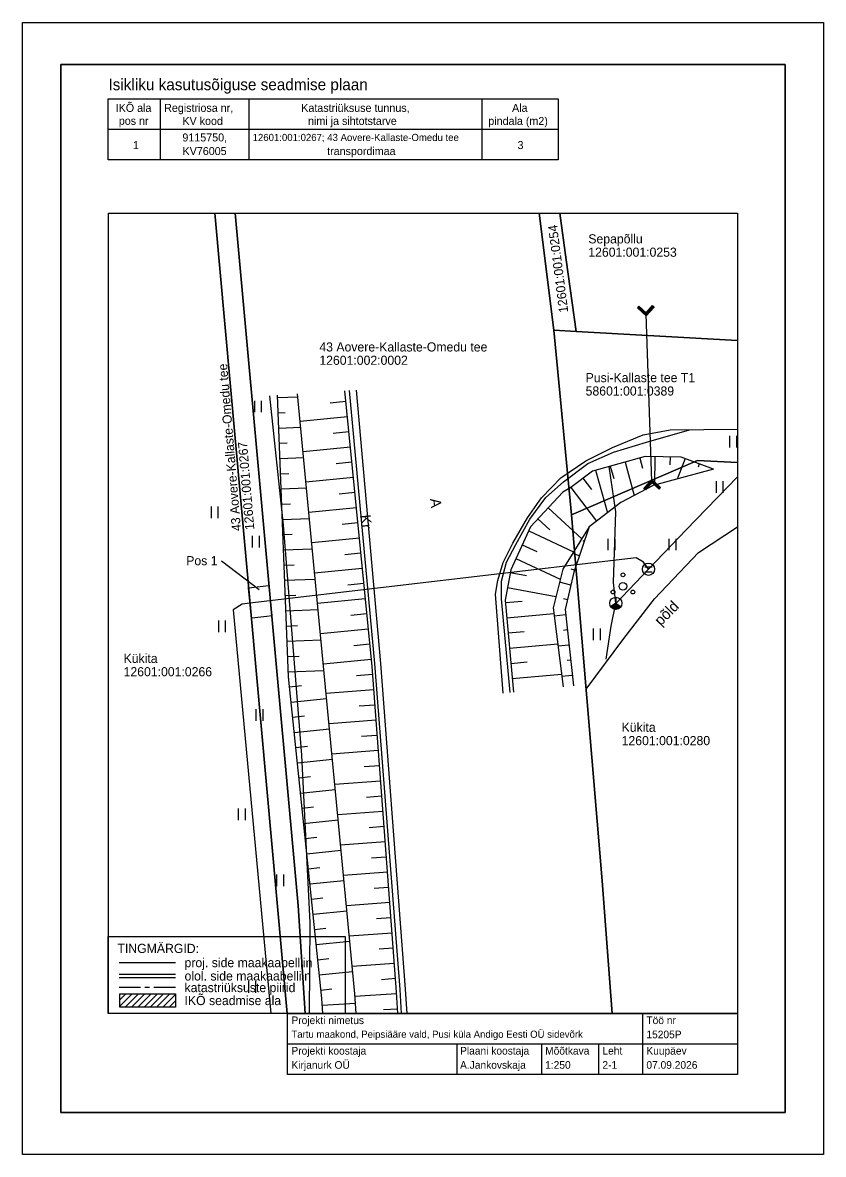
# Model space of a CAD drawing. Extents: x 683366.9 to 683419.4, y 6504541.6 to 6504615.8.
import ezdxf

# ---------------------------------------------------------------- set-up
doc = ezdxf.new("R2010")
doc.units = 0
for name, color, linetype in [('HALJASTUS', 7, 'Continuous'), ('KASUTUSALA', 7, 'Continuous'), ('PIIR', 7, 'Continuous'), ('PR_SIDE', 7, 'Continuous'), ('PUU', 7, 'Continuous'), ('RELJEEF', 7, 'Continuous'), ('SIKAEV', 7, 'Continuous'), ('SITRASS', 7, 'Continuous'), ('TEE', 7, 'Continuous'), ('TRUUP', 7, 'Continuous'), ('VORMISTUS', 7, 'Continuous')]:
    doc.layers.add(name, color=color, linetype=linetype)

msp = doc.modelspace()

# ---------------------------------------------------------------- linework, layer by layer
at = {"layer": 'HALJASTUS'}
for p, q in [((683382.127, 6504591.003), (683382.127, 6504590.242)), ((683382.583, 6504591.003), (683382.583, 6504590.242)), ((683413.292, 6504588.688), (683413.292, 6504587.927)), ((683413.747, 6504588.688), (683413.747, 6504587.927)), ((683412.397, 6504585.715), (683412.397, 6504584.954)), ((683412.852, 6504585.715), (683412.852, 6504584.954)), ((683379.285, 6504584.061), (683379.285, 6504583.3)), ((683379.74, 6504584.061), (683379.74, 6504583.3)), ((683381.983, 6504582.132), (683381.983, 6504581.371)), ((683382.438, 6504582.132), (683382.438, 6504581.371)), ((683405.305, 6504581.949), (683405.305, 6504581.188)), ((683405.76, 6504581.949), (683405.76, 6504581.188)), ((683409.309, 6504581.949), (683409.309, 6504581.188)), ((683409.764, 6504581.949), (683409.764, 6504581.188)), ((683379.767, 6504576.588), (683379.767, 6504575.827)), ((683380.222, 6504576.588), (683380.222, 6504575.827)), ((683404.34, 6504576.059), (683404.34, 6504575.298)), ((683404.795, 6504576.059), (683404.795, 6504575.298)), ((683382.224, 6504570.755), (683382.224, 6504569.993)), ((683382.679, 6504570.755), (683382.679, 6504569.993)), ((683381.068, 6504564.246), (683381.068, 6504563.485)), ((683381.523, 6504564.246), (683381.523, 6504563.485)), ((683383.573, 6504559.907), (683383.573, 6504559.146)), ((683384.028, 6504559.907), (683384.028, 6504559.146)), ((683381.742, 6504552.916), (683381.742, 6504552.155)), ((683382.197, 6504552.916), (683382.197, 6504552.155))]:
    msp.add_line(p, q, dxfattribs=at)
msp.add_lwpolyline([(683403.882, 6504572.085), (683406.35, 6504575.392), (683408.363, 6504577.994), (683411.241, 6504581.038), (683413.81, 6504582.721)], dxfattribs=at)
at = {"layer": 'KASUTUSALA'}
msp.add_lwpolyline([(683383.083, 6504578.873), (683383.264, 6504576.881), (683382.95, 6504576.844), (683382.95, 6504576.843), (683381.957, 6504576.727), (683381.931, 6504576.724), (683381.751, 6504578.716)], close=True, dxfattribs=at)
at = {"layer": 'PIIR'}
for p, q in [((683384.272, 6504550.807), (683379.529, 6504603.307)), ((683379.529, 6504603.307), (683384.272, 6504550.807))]:
    msp.add_line(p, q, dxfattribs=at)
for points in [[(683385.461, 6504550.807), (683384.99, 6504557.89), (683380.863, 6504603.307)], [(683380.863, 6504603.307), (683384.99, 6504557.89), (683385.461, 6504550.807)], [(683400.81, 6504603.307), (683401.76, 6504595.62), (683403.22, 6504595.54), (683402.57, 6504600.25), (683402.154, 6504603.307)], [(683405.591, 6504550.807), (683404.93, 6504559.51), (683402.93, 6504583.52), (683401.76, 6504595.62), (683400.81, 6504603.307)], [(683402.154, 6504603.307), (683402.57, 6504600.25), (683403.22, 6504595.54), (683413.81, 6504594.943)], [(683413.81, 6504594.943), (683403.22, 6504595.54), (683401.76, 6504595.62), (683402.93, 6504583.52), (683411.18, 6504587.08), (683413.81, 6504586.956)], [(683413.81, 6504586.956), (683411.18, 6504587.08), (683402.93, 6504583.52), (683404.93, 6504559.51), (683405.591, 6504550.807)]]:
    msp.add_lwpolyline(points, dxfattribs=at)
at = {"layer": 'PR_SIDE'}
for p, q in [((683405.828, 6504577.696), (683407.97, 6504579.943)), ((683407.737, 6504580.103), (683408.202, 6504580.103)), ((683407.737, 6504579.783), (683408.202, 6504579.783))]:
    msp.add_line(p, q, dxfattribs=at)
for points in [[(683407.97, 6504579.943), (683410.435, 6504582.529), (683413.81, 6504586.014)], [(683407.97, 6504579.943), (683407.639, 6504580.418), (683407.152, 6504580.701), (683381.841, 6504577.72)], [(683381.841, 6504577.72), (683381.328, 6504577.66), (683380.736, 6504577.291), (683383.213, 6504550.807)]]:
    msp.add_lwpolyline(points, dxfattribs=at)
msp.add_circle((683407.97, 6504579.943), 0.4, dxfattribs=at)
at = {"layer": 'PUU'}
for centre, radius in [((683406.294, 6504579.574), 0.125), ((683405.644, 6504578.449), 0.125), ((683406.294, 6504578.824), 0.25), ((683406.944, 6504578.449), 0.125)]:
    msp.add_circle(centre, radius, dxfattribs=at)
at = {"layer": 'RELJEEF'}
for p, q in [((683383.661, 6504591.209), (683384.973, 6504591.259)), ((683388.128, 6504590.944), (683387.096, 6504590.843)), ((683383.7, 6504590.21), (683384.156, 6504590.227)), ((683388.226, 6504589.949), (683385.128, 6504589.644)), ((683383.738, 6504589.21), (683385.164, 6504589.265)), ((683388.324, 6504588.954), (683387.29, 6504588.852)), ((683383.776, 6504588.211), (683384.271, 6504588.23)), ((683388.422, 6504587.959), (683385.319, 6504587.653)), ((683383.815, 6504587.212), (683385.355, 6504587.271)), ((683388.52, 6504586.964), (683387.485, 6504586.862)), ((683405.467, 6504586.709), (683405.687, 6504585.905)), ((683406.432, 6504586.974), (683407.033, 6504584.779)), ((683407.396, 6504587.238), (683407.577, 6504586.577)), ((683408.383, 6504587.326), (683408.363, 6504585.459)), ((683409.383, 6504587.315), (683409.377, 6504586.787)), ((683410.366, 6504587.214), (683409.855, 6504585.863)), ((683411.301, 6504586.86), (683411.216, 6504586.635)), ((683383.853, 6504586.213), (683384.386, 6504586.233)), ((683388.618, 6504585.969), (683385.509, 6504585.662)), ((683403.669, 6504585.916), (683404.23, 6504585.177)), ((683404.503, 6504586.445), (683405.272, 6504583.637)), ((683412.237, 6504586.506), (683412.237, 6504586.506)), ((683383.891, 6504585.213), (683385.546, 6504585.277)), ((683402.873, 6504585.311), (683404.559, 6504583.089)), ((683388.716, 6504584.973), (683387.679, 6504584.871)), ((683383.93, 6504584.214), (683384.5, 6504584.236)), ((683388.815, 6504583.978), (683385.7, 6504583.671)), ((683401.4, 6504583.978), (683403.59, 6504581.939)), ((683383.968, 6504583.215), (683385.737, 6504583.283)), ((683388.913, 6504582.983), (683387.874, 6504582.881)), ((683400.719, 6504583.246), (683401.495, 6504582.523)), ((683384.006, 6504582.216), (683384.615, 6504582.239)), ((683400.114, 6504582.462), (683403.062, 6504581.098)), ((683404.082, 6504582.722), (683404.082, 6504582.722)), ((683389.011, 6504581.988), (683385.891, 6504581.68)), ((683399.694, 6504581.555), (683400.638, 6504581.118)), ((683403.764, 6504581.774), (683403.687, 6504581.799)), ((683384.045, 6504581.216), (683385.928, 6504581.289)), ((683389.109, 6504580.993), (683388.068, 6504580.89)), ((683403.446, 6504580.826), (683402.987, 6504580.979)), ((683384.083, 6504580.217), (683384.73, 6504580.242)), ((683389.207, 6504579.998), (683386.081, 6504579.689)), ((683399.274, 6504580.647), (683402.184, 6504579.301)), ((683403.129, 6504579.877), (683402.899, 6504579.954)), ((683384.121, 6504579.218), (683386.119, 6504579.294)), ((683398.901, 6504579.725), (683399.982, 6504579.528)), ((683389.305, 6504579.002), (683388.262, 6504578.9)), ((683398.722, 6504578.741), (683401.904, 6504578.161)), ((683402.886, 6504578.908), (683402.132, 6504579.087)), ((683384.16, 6504578.219), (683384.845, 6504578.245)), ((683389.403, 6504578.007), (683386.272, 6504577.699)), ((683398.586, 6504577.755), (683399.683, 6504577.855)), ((683402.655, 6504577.935), (683402.401, 6504577.995)), ((683384.198, 6504577.219), (683386.31, 6504577.3)), ((683389.501, 6504577.012), (683388.457, 6504576.909)), ((683398.677, 6504576.759), (683401.769, 6504577.041)), ((683402.539, 6504576.955), (683401.79, 6504576.873)), ((683384.236, 6504576.22), (683384.959, 6504576.248)), ((683389.599, 6504576.017), (683386.463, 6504575.708)), ((683398.767, 6504575.763), (683399.81, 6504575.858)), ((683402.648, 6504575.96), (683402.404, 6504575.934)), ((683384.275, 6504575.221), (683386.501, 6504575.306)), ((683389.698, 6504575.022), (683388.651, 6504574.918)), ((683398.858, 6504574.768), (683402.021, 6504575.056)), ((683402.756, 6504574.966), (683402.042, 6504574.888)), ((683384.313, 6504574.222), (683385.074, 6504574.251)), ((683389.796, 6504574.026), (683386.653, 6504573.717)), ((683384.351, 6504573.222), (683386.692, 6504573.312)), ((683398.949, 6504573.772), (683400.015, 6504573.869)), ((683402.865, 6504573.972), (683402.632, 6504573.947)), ((683389.881, 6504573.03), (683388.835, 6504572.952)), ((683399.039, 6504572.776), (683402.273, 6504573.07)), ((683402.973, 6504572.978), (683402.294, 6504572.904)), ((683384.433, 6504572.226), (683385.213, 6504572.307)), ((683389.956, 6504572.033), (683386.836, 6504571.799)), ((683384.536, 6504571.231), (683386.867, 6504571.472)), ((683390.031, 6504571.036), (683388.998, 6504570.958)), ((683384.638, 6504570.237), (683385.413, 6504570.317)), ((683390.106, 6504570.039), (683387.025, 6504569.807)), ((683384.741, 6504569.242), (683387.056, 6504569.481)), ((683390.181, 6504569.041), (683389.16, 6504568.965)), ((683384.844, 6504568.247), (683385.613, 6504568.327)), ((683390.256, 6504568.044), (683387.214, 6504567.816)), ((683384.947, 6504567.253), (683387.245, 6504567.49)), ((683390.33, 6504567.047), (683389.323, 6504566.971)), ((683385.05, 6504566.258), (683385.813, 6504566.337)), ((683390.405, 6504566.05), (683387.403, 6504565.825)), ((683385.152, 6504565.263), (683387.434, 6504565.499)), ((683385.255, 6504564.268), (683386.013, 6504564.347)), ((683390.48, 6504565.053), (683389.486, 6504564.978)), ((683390.555, 6504564.055), (683387.592, 6504563.833)), ((683385.358, 6504563.274), (683387.623, 6504563.508)), ((683390.63, 6504563.058), (683389.649, 6504562.985)), ((683385.461, 6504562.279), (683386.213, 6504562.357)), ((683385.563, 6504561.284), (683387.812, 6504561.517)), ((683390.704, 6504562.061), (683387.781, 6504561.842)), ((683390.779, 6504561.064), (683389.812, 6504560.991)), ((683385.666, 6504560.29), (683386.413, 6504560.367)), ((683390.854, 6504560.067), (683387.971, 6504559.85)), ((683385.769, 6504559.295), (683388.001, 6504559.526)), ((683390.929, 6504559.069), (683389.974, 6504558.998)), ((683385.872, 6504558.3), (683386.613, 6504558.377)), ((683391.004, 6504558.072), (683388.16, 6504557.859)), ((683385.975, 6504557.305), (683388.19, 6504557.534)), ((683391.079, 6504557.075), (683390.137, 6504557.004)), ((683386.077, 6504556.311), (683386.813, 6504556.387)), ((683386.18, 6504555.316), (683388.379, 6504555.543)), ((683391.153, 6504556.078), (683388.349, 6504555.867)), ((683391.228, 6504555.081), (683390.3, 6504555.011)), ((683386.283, 6504554.321), (683387.013, 6504554.397)), ((683391.303, 6504554.084), (683388.538, 6504553.876)), ((683386.386, 6504553.327), (683388.569, 6504553.552)), ((683391.378, 6504553.086), (683390.463, 6504553.018)), ((683386.488, 6504552.332), (683387.213, 6504552.407)), ((683391.451, 6504552.089), (683388.719, 6504551.92)), ((683386.576, 6504551.336), (683388.749, 6504551.484)), ((683391.513, 6504551.091), (683390.604, 6504551.035))]:
    msp.add_line(p, q, dxfattribs=at)
for points in [[(683386.612, 6504550.807), (683386.546, 6504551.775), (683384.364, 6504572.893), (683383.655, 6504591.362)], [(683388.795, 6504550.807), (683388.707, 6504552.098), (683386.71, 6504573.129), (683384.955, 6504591.445)], [(683391.531, 6504550.807), (683391.445, 6504552.197), (683389.841, 6504573.563), (683388.059, 6504591.641)], [(683412.237, 6504586.506), (683410.12, 6504587.307), (683407.743, 6504587.333), (683404.29, 6504586.387), (683402.87, 6504585.309)], [(683412.237, 6504586.506), (683408.284, 6504585.438), (683406.155, 6504584.316), (683404.082, 6504582.722), (683404.082, 6504582.722)], [(683402.87, 6504585.309), (683402.87, 6504585.309), (683402.349, 6504584.997), (683400.237, 6504582.728), (683398.935, 6504579.914), (683398.571, 6504577.917), (683399.12, 6504571.889)], [(683404.082, 6504582.722), (683402.347, 6504579.959), (683401.721, 6504577.418), (683402.38, 6504572.223)], [(683404.082, 6504582.722), (683403.085, 6504579.748), (683402.503, 6504577.293), (683403.048, 6504572.292)]]:
    msp.add_lwpolyline(points, dxfattribs=at)
at = {"layer": 'SIKAEV'}
for p, q in [((683405.831, 6504577.71), (683405.499, 6504577.49)), ((683405.831, 6504578.11), (683405.831, 6504577.71)), ((683405.831, 6504577.71), (683406.163, 6504577.49))]:
    msp.add_line(p, q, dxfattribs=at)
msp.add_circle((683405.831, 6504577.71), 0.4, dxfattribs=at)
for radius in [0.38, 0.36, 0.34, 0.32, 0.3, 0.28, 0.26, 0.24, 0.22, 0.2, 0.18, 0.16, 0.14, 0.12, 0.1, 0.08, 0.06, 0.04]:
    msp.add_arc((683405.831, 6504577.71), radius, 213.53047, 326.46953, dxfattribs=at)
at = {"layer": 'SITRASS'}
for points in [[(683385.753, 6504550.807), (683385.785, 6504556.743), (683385.248, 6504567.755), (683384.036, 6504582.83), (683383.136, 6504591.331)], [(683405.195, 6504574.053), (683405.532, 6504576.217), (683405.831, 6504577.71), (683405.671, 6504579.075), (683405.836, 6504583.714), (683405.386, 6504586.687)]]:
    msp.add_lwpolyline(points, dxfattribs=at)
at = {"layer": 'TEE'}
msp.add_line((683409.392, 6504589.092), (683413.81, 6504589.126), dxfattribs=at)
for points in [[(683391.772, 6504550.807), (683391.678, 6504552.377), (683390.017, 6504573.76), (683388.371, 6504591.661)], [(683392.145, 6504550.807), (683392.042, 6504552.398), (683390.421, 6504573.765), (683388.835, 6504591.69)], [(683398.434, 6504571.819), (683397.934, 6504578.302), (683398.099, 6504579.204), (683398.449, 6504580.382), (683399.075, 6504581.656), (683400.042, 6504583.318), (683400.952, 6504584.633), (683402.217, 6504585.941), (683403.853, 6504587.052), (683405.602, 6504587.93), (683407.625, 6504588.773), (683409.392, 6504589.092)], [(683398.891, 6504571.866), (683398.331, 6504578.013), (683398.331, 6504579.152), (683398.663, 6504580.415), (683399.274, 6504581.57), (683400.189, 6504583.227), (683401.247, 6504584.642), (683402.407, 6504585.68), (683403.985, 6504586.892), (683405.667, 6504587.617), (683407.83, 6504588.292), (683410.648, 6504589.102)]]:
    msp.add_lwpolyline(points, dxfattribs=at)
at = {"layer": 'TRUUP'}
for p, q in [((683407.343, 6504597.208), (683407.246, 6504597.103)), ((683407.246, 6504597.103), (683407.816, 6504596.573)), ((683407.266, 6504597.125), (683407.289, 6504597.064)), ((683407.285, 6504597.145), (683407.329, 6504597.026)), ((683407.294, 6504597.156), (683407.812, 6504596.674)), ((683407.304, 6504597.166), (683407.37, 6504596.988)), ((683407.323, 6504597.186), (683407.411, 6504596.95)), ((683407.342, 6504597.207), (683407.451, 6504596.912)), ((683407.343, 6504597.208), (683407.808, 6504596.775)), ((683407.382, 6504597.171), (683407.492, 6504596.875)), ((683407.423, 6504597.133), (683407.533, 6504596.837)), ((683407.463, 6504597.096), (683407.573, 6504596.799)), ((683407.504, 6504597.058), (683407.614, 6504596.761)), ((683407.545, 6504597.02), (683407.655, 6504596.723)), ((683407.808, 6504596.775), (683408.242, 6504597.24)), ((683407.812, 6504596.674), (683408.294, 6504597.192)), ((683407.816, 6504596.573), (683408.346, 6504597.143)), ((683408.028, 6504597.011), (683408.083, 6504596.861)), ((683408.047, 6504597.031), (683408.102, 6504596.882)), ((683408.066, 6504597.052), (683408.122, 6504596.902)), ((683408.085, 6504597.072), (683408.141, 6504596.923)), ((683408.104, 6504597.093), (683408.16, 6504596.943)), ((683408.123, 6504597.113), (683408.179, 6504596.964)), ((683408.142, 6504597.134), (683408.198, 6504596.984)), ((683408.161, 6504597.154), (683408.217, 6504597.005)), ((683408.181, 6504597.175), (683408.236, 6504597.025)), ((683408.2, 6504597.195), (683408.255, 6504597.046)), ((683408.219, 6504597.216), (683408.274, 6504597.066)), ((683408.238, 6504597.236), (683408.293, 6504597.087)), ((683408.242, 6504597.24), (683408.346, 6504597.143)), ((683408.274, 6504597.21), (683408.312, 6504597.107)), ((683408.315, 6504597.172), (683408.331, 6504597.128)), ((683407.585, 6504596.982), (683407.695, 6504596.685)), ((683407.626, 6504596.944), (683407.736, 6504596.648)), ((683407.667, 6504596.906), (683407.777, 6504596.61)), ((683407.707, 6504596.869), (683407.817, 6504596.574)), ((683407.748, 6504596.831), (683407.836, 6504596.595)), ((683407.789, 6504596.793), (683407.855, 6504596.615)), ((683408.193, 6504585.728), (683407.812, 6504596.674)), ((683407.818, 6504596.785), (683407.874, 6504596.636)), ((683407.837, 6504596.806), (683407.893, 6504596.656)), ((683407.856, 6504596.826), (683407.912, 6504596.677)), ((683407.876, 6504596.847), (683407.931, 6504596.697)), ((683407.895, 6504596.867), (683407.95, 6504596.718)), ((683407.914, 6504596.888), (683407.969, 6504596.738)), ((683407.933, 6504596.908), (683407.988, 6504596.759)), ((683407.952, 6504596.929), (683408.007, 6504596.779)), ((683407.971, 6504596.949), (683408.026, 6504596.8)), ((683407.99, 6504596.97), (683408.045, 6504596.82)), ((683408.009, 6504596.99), (683408.064, 6504596.841)), ((683408.188, 6504585.828), (683407.665, 6504585.252)), ((683407.771, 6504585.156), (683407.665, 6504585.252)), ((683407.697, 6504585.223), (683407.68, 6504585.267)), ((683407.738, 6504585.186), (683407.698, 6504585.288)), ((683407.774, 6504585.16), (683407.717, 6504585.309)), ((683408.193, 6504585.728), (683407.718, 6504585.204)), ((683407.793, 6504585.181), (683407.736, 6504585.33)), ((683407.812, 6504585.202), (683407.755, 6504585.35)), ((683408.198, 6504585.627), (683407.771, 6504585.156)), ((683407.831, 6504585.222), (683407.774, 6504585.371)), ((683407.85, 6504585.243), (683407.792, 6504585.392)), ((683407.869, 6504585.264), (683407.811, 6504585.413)), ((683407.887, 6504585.285), (683407.83, 6504585.433)), ((683407.906, 6504585.305), (683407.849, 6504585.454)), ((683407.925, 6504585.326), (683407.868, 6504585.475)), ((683407.944, 6504585.347), (683407.887, 6504585.496)), ((683407.963, 6504585.368), (683407.905, 6504585.516)), ((683407.981, 6504585.388), (683407.924, 6504585.537)), ((683408, 6504585.409), (683407.943, 6504585.558)), ((683408.019, 6504585.43), (683407.962, 6504585.579)), ((683408.038, 6504585.45), (683407.981, 6504585.599)), ((683408.057, 6504585.471), (683407.999, 6504585.62)), ((683408.075, 6504585.492), (683408.018, 6504585.641)), ((683408.094, 6504585.513), (683408.037, 6504585.661)), ((683408.113, 6504585.533), (683408.056, 6504585.682)), ((683408.132, 6504585.554), (683408.075, 6504585.703)), ((683408.151, 6504585.575), (683408.093, 6504585.724)), ((683408.169, 6504585.596), (683408.112, 6504585.744)), ((683408.188, 6504585.616), (683408.131, 6504585.765)), ((683408.218, 6504585.609), (683408.15, 6504585.786)), ((683408.259, 6504585.572), (683408.169, 6504585.807)), ((683408.3, 6504585.534), (683408.187, 6504585.827)), ((683408.765, 6504585.305), (683408.188, 6504585.828)), ((683408.717, 6504585.253), (683408.193, 6504585.728)), ((683408.669, 6504585.2), (683408.198, 6504585.627)), ((683408.341, 6504585.497), (683408.228, 6504585.792)), ((683408.382, 6504585.46), (683408.269, 6504585.755)), ((683408.424, 6504585.422), (683408.31, 6504585.718)), ((683408.465, 6504585.385), (683408.351, 6504585.68)), ((683408.506, 6504585.348), (683408.392, 6504585.643)), ((683408.547, 6504585.31), (683408.433, 6504585.606)), ((683408.588, 6504585.273), (683408.475, 6504585.568)), ((683408.629, 6504585.236), (683408.516, 6504585.531)), ((683408.67, 6504585.201), (683408.557, 6504585.494)), ((683408.688, 6504585.221), (683408.598, 6504585.456)), ((683408.707, 6504585.242), (683408.639, 6504585.419)), ((683408.669, 6504585.2), (683408.765, 6504585.305)), ((683408.726, 6504585.263), (683408.68, 6504585.382)), ((683408.745, 6504585.283), (683408.721, 6504585.344))]:
    msp.add_line(p, q, dxfattribs=at)
at = {"layer": 'VORMISTUS'}
for p, q in [((683375.946, 6504610.812), (683375.946, 6504606.812)), ((683381.771, 6504610.812), (683381.771, 6504606.812)), ((683397.046, 6504610.812), (683397.046, 6504606.812)), ((683372.546, 6504608.812), (683402.046, 6504608.812)), ((683382.447, 6504578.603), (683379.98, 6504580.48)), ((683373.256, 6504554.135), (683376.95, 6504554.135)), ((683373.256, 6504553.373), (683376.95, 6504553.373)), ((683374.666, 6504552.5), (683373.255, 6504552.5)), ((683373.256, 6504553.152), (683376.95, 6504553.152)), ((683375.248, 6504552.5), (683374.957, 6504552.5)), ((683376.95, 6504552.5), (683375.539, 6504552.5)), ((683374.119, 6504552.087), (683373.309, 6504551.277)), ((683373.707, 6504552.087), (683373.309, 6504551.689)), ((683374.531, 6504552.087), (683373.657, 6504551.213)), ((683374.943, 6504552.087), (683374.069, 6504551.213)), ((683375.355, 6504552.087), (683374.481, 6504551.213)), ((683375.766, 6504552.087), (683374.893, 6504551.213)), ((683376.178, 6504552.087), (683375.305, 6504551.213)), ((683376.59, 6504552.087), (683375.716, 6504551.213)), ((683376.95, 6504552.035), (683376.128, 6504551.213)), ((683376.95, 6504551.623), (683376.54, 6504551.213)), ((683407.583, 6504550.807), (683407.583, 6504548.807)), ((683384.31, 6504548.807), (683413.81, 6504548.807)), ((683395.403, 6504548.807), (683395.403, 6504546.807)), ((683400.946, 6504548.807), (683400.946, 6504546.807)), ((683404.699, 6504548.807), (683404.699, 6504546.807)), ((683407.583, 6504548.807), (683407.583, 6504546.807))]:
    msp.add_line(p, q, dxfattribs=at)
for points in [[(683366.935, 6504615.807), (683419.435, 6504615.807), (683419.435, 6504541.557), (683366.935, 6504541.557)], [(683369.435, 6504544.307), (683416.935, 6504544.307), (683416.935, 6504613.057), (683369.435, 6504613.057)], [(683369.435, 6504613.057), (683416.935, 6504613.057), (683416.935, 6504544.307), (683369.435, 6504544.307)], [(683372.546, 6504610.812), (683402.046, 6504610.812), (683402.046, 6504606.812), (683372.546, 6504606.812)], [(683413.81, 6504550.807), (683372.56, 6504550.807), (683372.56, 6504603.307), (683413.81, 6504603.307)], [(683372.55, 6504550.8), (683372.55, 6504555.86), (683388.08, 6504555.86), (683388.08, 6504550.8)], [(683373.309, 6504552.087), (683376.95, 6504552.087), (683376.95, 6504551.213), (683373.309, 6504551.213)], [(683384.31, 6504550.807), (683413.81, 6504550.807), (683413.81, 6504546.807), (683384.31, 6504546.807)]]:
    msp.add_lwpolyline(points, close=True, dxfattribs=at)

# ---------------------------------------------------------------- texts
at = {"layer": 'HALJASTUS'}
msp.add_text('põld', height=0.7, rotation=45.0225, dxfattribs=at).set_placement((683408.772, 6504576.194))
at = {"layer": 'PIIR'}
for s, rotation, p in [('12601:001:0254', 97.33176, (683402.713, 6504596.817)), ('43 Aovere-Kallaste-Omedu tee', 94.78015, (683381.256, 6504582.477)), ('12601:001:0267', 94.78015, (683382.128, 6504582.55))]:
    msp.add_text(s, height=0.6, rotation=rotation, dxfattribs=at).set_placement(p)
for s, p in [('Sepapõllu', (683404.024, 6504601.322)), ('12601:001:0253', (683404.024, 6504600.447)), ('43 Aovere-Kallaste-Omedu tee', (683386.389, 6504594.231)), ('12601:002:0002', (683386.389, 6504593.356)), ('Pusi-Kallaste tee T1', (683403.848, 6504592.216)), ('58601:001:0389', (683403.848, 6504591.341)), ('Kükita', (683373.554, 6504573.797)), ('12601:001:0266', (683373.554, 6504572.922)), ('Kükita', (683406.21, 6504569.278)), ('12601:001:0280', (683406.21, 6504568.403))]:
    msp.add_text(s, height=0.6, dxfattribs=at).set_placement(p)
at = {"layer": 'TEE'}
for s, p in [('A', (683393.647, 6504584.561)), ('Kr', (683389.052, 6504583.489))]:
    msp.add_text(s, height=0.7, rotation=276.34328, dxfattribs=at).set_placement(p)
at = {"layer": 'VORMISTUS'}
for s, height, p in [('Isikliku kasutusõiguse seadmise plaan', 0.75, (683372.563, 6504611.374)), ('IKÕ ala', 0.525, (683373.036, 6504609.952)), ('Registriosa nr,', 0.525, (683376.214, 6504609.952)), ('Katastriüksuse tunnus,', 0.525, (683385.204, 6504609.952)), ('Ala', 0.525, (683399.026, 6504609.952)), ('KV kood', 0.525, (683377.411, 6504609.093)), ('nimi ja sihtotstarve', 0.525, (683385.649, 6504609.097)), ('pindala (m2)', 0.525, (683397.469, 6504609.093)), ('pos nr', 0.525, (683373.24, 6504609.101)), ('9115750,', 0.525, (683377.41, 6504608.012)), ('12601:001:0267; 43 Aovere-Kallaste-Omedu tee', 0.47, (683382.014, 6504608.039)), ('1', 0.525, (683374.171, 6504607.512)), ('KV76005', 0.525, (683377.42, 6504607.118)), ('transpordimaa', 0.525, (683386.9, 6504607.118)), ('3', 0.525, (683399.385, 6504607.512)), ('Pos 1', 0.6, (683377.66, 6504580.205)), ('TINGMÄRGID:', 0.6, (683373.15, 6504554.77)), ('proj. side maakaabelliin', 0.6, (683377.55, 6504553.835)), ('olol. side maakaabelliin', 0.6, (683377.55, 6504552.962)), ('katastriüksuste piirid', 0.6, (683377.55, 6504552.2)), ('IKÕ seadmise ala', 0.6, (683377.55, 6504551.35)), ('Projekti nimetus', 0.5, (683384.559, 6504550.103)), ('Töö nr', 0.5, (683407.832, 6504550.103)), ('Tartu maakond, Peipsiääre vald, Pusi küla Andigo Eesti OÜ sidevõrk', 0.47, (683384.559, 6504549.204)), ('15205P', 0.5, (683407.832, 6504549.174)), ('Projekti koostaja', 0.5, (683384.559, 6504548.103)), ('Plaani koostaja', 0.5, (683395.616, 6504548.103)), ('Mõõtkava', 0.5, (683401.195, 6504548.103)), ('Leht', 0.5, (683404.948, 6504548.103)), ('Kuupäev', 0.5, (683407.832, 6504548.103)), ('Kirjanurk OÜ', 0.5, (683384.559, 6504547.174)), ('A.Jankovskaja', 0.5, (683395.616, 6504547.174)), ('1:250', 0.5, (683401.195, 6504547.174)), ('2-1', 0.5, (683404.948, 6504547.174)), ('07.09.2026', 0.5, (683407.832, 6504547.174))]:
    msp.add_text(s, height=height, dxfattribs=at).set_placement(p)

doc.saveas('drawing.dxf')
